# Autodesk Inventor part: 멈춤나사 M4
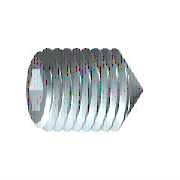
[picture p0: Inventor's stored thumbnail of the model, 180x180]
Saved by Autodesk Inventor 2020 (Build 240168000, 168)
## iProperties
Created: 2012-02
Part Number: 멈춤나사 M4
Material: 강철, 연강
Document SubType Name: Modeling
Standard: JIS B 1177 원추점
Designer: mdu-01
Standards Organization: JIS
Language: ko-KR
Size Designation: M4 x 10
Categories: <MemberInstance><Categories><Category DisplayName="조임쇠" InternalName="e4da775c-781d-43d5-af7c-5136215cf5a6" Mnemonic="FSTN"><Category DisplayName="볼트" InternalN
Density: 1 g/cm^3
Appearance: 강철
IsCustomPart: 1
Author: mdu-01
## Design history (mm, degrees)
sketch "스케치1"
  geometry: L1 (0, 0)-(6.833, 0); L2 (10, 1.155)-(10, 2); L3 (10, 2)-(0, 2); L4 (10, 1.155)-(7.5, 1.155); L5 (7.5, 1.155)-(6.833, 0); L6 (0, -0.4)-(0, 2.4) reference; L7 (0, 2)-(0, 0)
  constraints: 13 end point, 3 parallel, 1 collinear, 1 perpendicular, 1 point on line
  dimensions: "d0" = 2.5 distance of L2.start L4.end (= INTI); "d1" = 60 deg angle of L5 L1; "d2" = 4 diameter of L3 L1 (= NND); "d3" = 2.3094 diameter of L4 L1 (= 1.1547 x SW); "d5" = 10 distance from line of L2 L3.end (= NLG)
revolve "본체" sketch "스케치1" stored, may be unused: angle "d6" = 90 deg
sketch "스케치2"
  geometry: L1 (-0.577, 1)-(0.577, 1); L2 (0.577, 1)-(1.155, 0); L3 (1.155, 0)-(0.577, -1); L4 (0.577, -1)-(-0.577, -1); L5 (-0.577, -1)-(-1.155, 0); L6 (-1.155, 0)-(-0.577, 1); 3 further points
  constraints: 12 end point, 1 coincident, 1 horizontal, 13 other
extrude "슬롯" join sketch "스케치2" taper "d7" = 0 deg; stored distance "d21" = 10
workaxis "Work Axis1"
workplane "Work Plane1"
body "Solid1"
feature "스레드" dims "d12" = 10 (= NLG), "d13" = 0
chamfer "모따기1" distance "d8" = 1.03923 (computed from NND, SPD, FAWI); stored, may be unused: angle "d9" = 60 deg (= FAWI), second distance "d34" = 1.03923 (computed from NND, SPD, FAWI)
chamfer "모따기2" distance "d10" = 0.42941 (= -0.5 x GD1 + 0.5 x NND); stored, may be unused: angle "d11" = 60 deg (= FAWI), second distance "d35" = 0.42941 (= -0.5 x GD1 + 0.5 x NND)
other parameters: "NND" = 4 [user parameter; used in 5 equation terms], "NLG" = 10 [user parameter; used in 2 equation terms], "INTI" = 2.5 [user parameter; used in 1 equation term], "FAWI" = 60 deg [user parameter; used in 4 equation terms], "SW" = 2 [user parameter; used in 2 equation terms], "GD1" = 3.14117 (= THREADDIA - 1.2269 x PTC) [user parameter; used in 2 equation terms], "d4" = 0, "FAWI1" = 45 deg [user parameter], "SPD" = 0.4 [user parameter; used in 2 equation terms], "d36" = 0, "d37" = 0, "GUL" = 0.42941 (= 0.61345 x PTC) [user parameter], "TPU" = 14.28571 (computed from PTC) [user parameter], "TOA" = 30 deg [user parameter], "THREADDIA" = 4 [user parameter; used in 1 equation term], "PTC" = 0.7 [user parameter; used in 4 equation terms], "GAL" = 0.42941 (= 0.61345 x PTC) [user parameter], "E0" = 2.31 (= 1.155 x SW) [user parameter]
